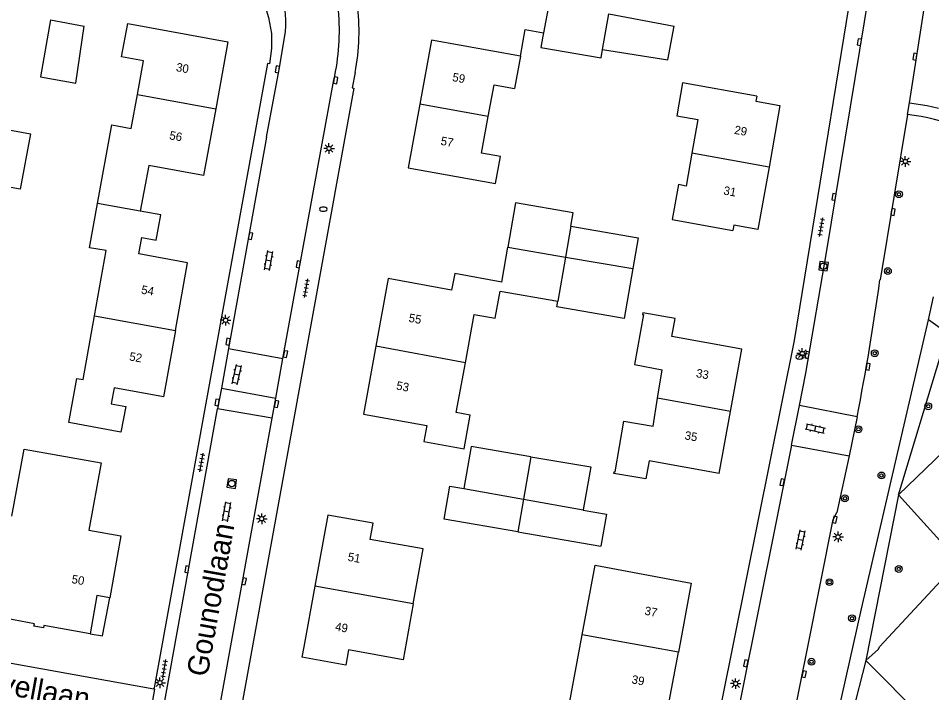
# Model space of a CAD drawing. Extents: x 132999 to 136000, y 398499 to 400501.
# Drawn here: x 133145.7 to 133253.2, y 398994.6 to 399074 of the extents above; entities that cross this region are included whole.
import ezdxf

# ---------------------------------------------------------------- set-up
doc = ezdxf.new("R2010")
doc.units = 0
for name, color, linetype in [('gg-afsc-erfafscheiding', 7, 'Continuous'), ('gg-afsc-muur', 7, 'Continuous'), ('gg-anno-huisnummerreeks BGT', 7, 'Continuous'), ('gg-anno-openbare ruimte label', 7, 'Continuous'), ('gg-bbg-bijgebouw', 7, 'Continuous'), ('gg-bbg-gedigitaliseerde bebouwing', 7, 'Continuous'), ('gg-bbg-gedigitaliseerde bijgebouw', 7, 'Continuous'), ('gg-bbg-hoofdgebouw', 7, 'Continuous'), ('gg-bbg-onder overbouw', 7, 'Continuous'), ('gg-bbg-pand overbouw', 7, 'Continuous'), ('gg-bbg-tussenscheiding', 7, 'Continuous'), ('gg-knt-verharding', 7, 'Continuous'), ('gt-grn-groengrens', 7, 'Continuous'), ('gt-grn-weggrens', 7, 'Continuous'), ('gt-symb-boom', 7, 'Continuous'), ('gt-symb-brandkraan', 7, 'Continuous'), ('gt-symb-klinker verharding', 7, 'Continuous'), ('gt-symb-kolk', 7, 'Continuous'), ('gt-symb-lichtmast', 7, 'Continuous'), ('gt-symb-rioolschacht', 7, 'Continuous'), ('gt-symb-tegel verharding', 7, 'Continuous')]:
    doc.layers.add(name, color=color, linetype=linetype)

# ---------------------------------------------------------------- blocks, each defined once
blk = doc.blocks.new('gt0-BOOM')
at = {"layer": 'gt-symb-boom'}
for radius in [0.4, 0.2]:
    blk.add_circle((0, 0), radius, dxfattribs=at)
blk = doc.blocks.new('gt0-KOLK')
at = {"layer": 'gt-symb-kolk'}
blk.add_lwpolyline([(0, 0), (0.37, 0), (0.37, 0.4), (-0.38, 0.4), (-0.38, 0), (0, 0)], dxfattribs=at)
blk = doc.blocks.new('gt0-TEG1')
at = {"layer": 'gt-symb-tegel verharding'}
for p, q in [((-1.12, 0), (1.12, 0)), ((-0.9, -0.25), (-0.9, 0.25)), ((-0.45, -0.25), (-0.45, 0.25)), ((0, -0.25), (0, 0.25)), ((0.45, -0.25), (0.45, 0.25)), ((0.9, -0.25), (0.9, 0.25))]:
    blk.add_line(p, q, dxfattribs=at)
blk = doc.blocks.new('gt0-LMAST')
at = {"layer": 'gt-symb-lichtmast'}
for p, q in [((-0.18, 0.17), (-0.45, 0.44)), ((-0.01, 0.25), (-0.01, 0.62)), ((0.17, 0.17), (0.44, 0.44)), ((-0.26, 0), (-0.63, 0)), ((-0.18, -0.18), (-0.45, -0.45)), ((-0.01, -0.25), (-0.01, -0.63)), ((0.44, -0.45), (0.17, -0.18)), ((0.24, 0), (0.62, 0))]:
    blk.add_line(p, q, dxfattribs=at)
blk.add_circle((-0.01, 0), 0.25, dxfattribs=at)
blk = doc.blocks.new('gt0-KL1')
at = {"layer": 'gt-symb-klinker verharding'}
for p, q in [((-1.15, 0.3), (1.15, 0.3)), ((-1, -0.3), (-1, 0.3)), ((-0.5, 0.3), (-0.5, 0.45)), ((0, -0.3), (0, 0.3)), ((0.5, 0.3), (0.5, 0.45)), ((1, -0.3), (1, 0.3)), ((-1.15, -0.3), (1.15, -0.3)), ((-0.5, -0.45), (-0.5, -0.3)), ((0.5, -0.45), (0.5, -0.3))]:
    blk.add_line(p, q, dxfattribs=at)
blk = doc.blocks.new('gt0-BR')
at = {"layer": 'gt-symb-brandkraan'}
for centre, radius, start, end in [((-0.24, 0), 0.206, 107.5669, 252.4331), ((0.6, -2.66), 3, 106.892, 107.5669), ((0, -0.69), 0.938, 73.108, 106.892), ((-0.6, -2.66), 3, 72.4331, 73.108), ((0.24, 0), 0.206, 287.567, 72.4331), ((0.6, 2.66), 3, 252.4331, 253.108), ((0, 0.69), 0.938, 253.108, 286.8921), ((-0.6, 2.66), 3, 286.8921, 287.567)]:
    blk.add_arc(centre, radius, start, end, dxfattribs=at)
blk = doc.blocks.new('gt0-RS')
at = {"layer": 'gt-symb-rioolschacht'}
blk.add_lwpolyline([(-0.5, -0.5), (0.5, -0.5), (0.5, 0.5), (-0.5, 0.5)], close=True, dxfattribs=at)
blk.add_circle((0, 0), 0.375, dxfattribs=at)

msp = doc.modelspace()

# ---------------------------------------------------------------- linework, layer by layer
at = {"layer": 'gg-afsc-erfafscheiding'}
msp.add_line((133252.84, 399038.49), (133253.46, 399041.19), dxfattribs=at)
msp.add_lwpolyline([(133239.4, 398979.64), (133244.97, 399004.49), (133252.84, 399038.49)], dxfattribs=at)
at = {"layer": 'gg-afsc-muur'}
msp.add_lwpolyline([(133204.83, 399069.52), (133205.39, 399072.69), (133207.56, 399072.29)], dxfattribs=at)
at = {"layer": 'gg-bbg-bijgebouw'}
for p, q in [((133208.22, 399075.81), (133207.56, 399072.29)), ((133149.54, 399073.82), (133153.47, 399073.05)), ((133207.56, 399072.29), (133207.48, 399071.87)), ((133213.13, 399021.2), (133212.22, 399016.11))]:
    msp.add_line(p, q, dxfattribs=at)
msp.add_lwpolyline([(133212.22, 399016.11), (133212.22, 399016.09), (133214.95, 399015.6), (133214.28, 399011.86)], dxfattribs=at)
at = {"layer": 'gg-bbg-gedigitaliseerde bebouwing'}
for p, q in [((133204.83, 399069.52), (133204.14, 399065.74)), ((133202.65, 399042.93), (133203.36, 399047.05)), ((133202.65, 399042.93), (133197.1, 399043.95)), ((133202.45, 399041.87), (133209.24, 399040.7)), ((133210.6, 398993.37), (133212.1, 399001.43))]:
    msp.add_line(p, q, dxfattribs=at)
for points in [[(133159.75, 399065.03), (133160.47, 399068.98), (133157.89, 399069.44), (133158.61, 399073.38)], [(133201.05, 399062.44), (133201.73, 399066.18), (133204.14, 399065.74)], [(133232.64, 399064.84), (133223.92, 399066.39), (133223.23, 399062.52), (133225.71, 399062.08), (133225, 399058.1)], [(133155.07, 399052.2), (133156.74, 399061.44), (133159.03, 399061.03), (133159.75, 399065.03)], [(133191.62, 399056.39), (133201.89, 399054.53), (133202.47, 399057.71), (133200.26, 399058.11), (133201.05, 399062.44)], [(133225, 399058.1), (133224.32, 399054.25), (133223.43, 399054.41), (133222.7, 399050.29), (133229.82, 399049.03)], [(133154.69, 399038.96), (133156.06, 399046.64), (133154.13, 399046.99), (133155.07, 399052.2)], [(133198.36, 399033.44), (133199.4, 399039.13), (133201.86, 399038.68), (133202.45, 399041.87)], [(133157.82, 399025.28), (133151.68, 399026.42), (133152.61, 399031.6), (133153.35, 399031.47), (133154.69, 399038.96)], [(133193.48, 399024.18), (133198.19, 399023.32), (133198.92, 399027.27), (133197.28, 399027.57), (133198.36, 399033.44)], [(133144.99, 399015.4), (133146.41, 399023.28), (133155.47, 399021.65)], [(133192.21, 399005.05), (133193.39, 399011.52), (133187.13, 399012.65), (133187.48, 399014.54), (133182.15, 399015.51)], [(133212.1, 399001.43), (133213.61, 399009.6), (133224.93, 399007.49)], [(133192.21, 399005.05), (133191.02, 398998.48), (133184.6, 398999.65), (133184.27, 398997.86), (133179.11, 398998.8)]]:
    msp.add_lwpolyline(points, dxfattribs=at)
at = {"layer": 'gg-bbg-gedigitaliseerde bijgebouw'}
for p, q in [((133215.23, 399074.51), (133222.92, 399073.07)), ((133206.05, 399022.36), (133213.13, 399021.2)), ((133204.53, 399013.54), (133214.28, 399011.86))]:
    msp.add_line(p, q, dxfattribs=at)
for points in [[(133149.54, 399073.82), (133148.36, 399067.1), (133152.52, 399066.34), (133153.47, 399073.05)], [(133214.49, 399070.31), (133222.17, 399069.1), (133222.92, 399073.07)], [(133207.48, 399071.87), (133207.24, 399070.57), (133214.33, 399069.35), (133214.49, 399070.31)], [(133145.97, 399053.86), (133140.05, 399054.95), (133141.19, 399061.49), (133147.15, 399060.38), (133145.97, 399053.86)], [(133210.78, 399049.51), (133211.05, 399051.08), (133204.25, 399052.26), (133203.36, 399047.05)], [(133210.78, 399049.51), (133218.68, 399048.15), (133218.06, 399044.53)], [(133218.06, 399044.53), (133217.05, 399038.65), (133209.12, 399040.02), (133209.24, 399040.7)], [(133206.05, 399022.36), (133199.05, 399023.59), (133198.16, 399018.64)], [(133204.53, 399013.54), (133195.85, 399015.04), (133196.52, 399018.93), (133198.16, 399018.64)]]:
    msp.add_lwpolyline(points, dxfattribs=at)
at = {"layer": 'gg-bbg-hoofdgebouw'}
for p, q in [((133194.37, 399071.42), (133192.98, 399063.9)), ((133204.83, 399069.52), (133194.37, 399071.42)), ((133192.98, 399063.9), (133191.62, 399056.39)), ((133229.55, 399027.71), (133230.89, 399035.05)), ((133220.97, 399029.29), (133221.51, 399032.62)), ((133228.22, 399020.41), (133229.55, 399027.71)), ((133182.15, 399015.51), (133180.63, 399007.16)), ((133224.93, 399007.49), (133223.42, 398999.37)), ((133221.88, 398991.28), (133223.42, 398999.37))]:
    msp.add_line(p, q, dxfattribs=at)
for points in [[(133158.61, 399073.38), (133170.4, 399071.23), (133168.97, 399063.35)], [(133232.64, 399064.84), (133232.52, 399064.23), (133235.38, 399063.71), (133234.09, 399056.45)], [(133168.97, 399063.35), (133167.54, 399055.48), (133161.08, 399056.68), (133160.08, 399051.29)], [(133234.09, 399056.45), (133232.79, 399049.14), (133229.93, 399049.65), (133229.82, 399049.03)], [(133164.22, 399037.24), (133165.64, 399045.2), (133159.92, 399046.26), (133160.27, 399048.17), (133161.94, 399047.86), (133162.49, 399050.85), (133160.08, 399051.29)], [(133197.1, 399043.95), (133196.72, 399041.99), (133189.28, 399043.35), (133187.82, 399035.38)], [(133230.89, 399035.05), (133222.66, 399036.55), (133223.04, 399038.64), (133219.24, 399039.33), (133219.2, 399039.13), (133219.32, 399039.11), (133218.25, 399033.22), (133221.51, 399032.62)], [(133164.22, 399037.24), (133162.82, 399029.42), (133157.03, 399030.48), (133156.68, 399028.59), (133158.37, 399028.28), (133157.82, 399025.28)], [(133187.82, 399035.38), (133186.35, 399027.41), (133193.83, 399026.04), (133193.48, 399024.18)], [(133228.22, 399020.41), (133219.97, 399021.9), (133219.58, 399019.76), (133215.84, 399020.42), (133215.87, 399020.62), (133215.97, 399020.61), (133216.99, 399026.55), (133220.44, 399025.96), (133220.97, 399029.29)], [(133155.47, 399021.65), (133154.03, 399013.75), (133157.79, 399013.07), (133156.49, 399005.77)], [(133180.63, 399007.16), (133179.33, 399000), (133179.11, 398998.8)], [(133154.18, 399001.52), (133148.73, 399002.5), (133148.68, 399002.24), (133147.58, 399002.45), (133147.63, 399002.71), (133144.35, 399003.32)]]:
    msp.add_lwpolyline(points, dxfattribs=at)
at = {"layer": 'gg-bbg-onder overbouw'}
msp.add_lwpolyline([(133156.49, 399005.77), (133154.99, 399006.04), (133154.18, 399001.52)], dxfattribs=at)
at = {"layer": 'gg-bbg-pand overbouw'}
msp.add_lwpolyline([(133154.18, 399001.52), (133155.66, 399001.28), (133156.49, 399005.77)], dxfattribs=at)
at = {"layer": 'gg-bbg-tussenscheiding'}
for p, q in [((133214.49, 399070.31), (133215.23, 399074.51)), ((133159.75, 399065.03), (133168.97, 399063.35)), ((133201.05, 399062.44), (133192.98, 399063.9)), ((133234.09, 399056.45), (133225, 399058.1)), ((133160.08, 399051.29), (133155.07, 399052.2)), ((133210.78, 399049.51), (133210.15, 399045.89)), ((133203.36, 399047.05), (133210.15, 399045.89)), ((133210.15, 399045.89), (133209.24, 399040.7)), ((133210.15, 399045.89), (133218.06, 399044.53)), ((133154.69, 399038.96), (133164.22, 399037.24)), ((133198.36, 399033.44), (133187.82, 399035.38)), ((133229.55, 399027.71), (133220.97, 399029.29)), ((133206.05, 399022.36), (133205.19, 399017.37)), ((133198.16, 399018.64), (133205.19, 399017.37)), ((133205.19, 399017.37), (133204.53, 399013.54)), ((133205.19, 399017.37), (133212.22, 399016.11)), ((133192.21, 399005.05), (133180.63, 399007.16)), ((133219.96, 399000), (133212.1, 399001.43)), ((133223.42, 398999.37), (133219.96, 399000))]:
    msp.add_line(p, q, dxfattribs=at)
at = {"layer": 'gg-knt-verharding'}
for p, q in [((133250.61, 399064.04), (133252.47, 399075.91)), ((133174.89, 399067.8), (133161.73, 398995.19)), ((133181.4, 399058.83), (133182.88, 399066.73)), ((133185.23, 399065.78), (133167.57, 398968.5)), ((133250.38, 399062.67), (133250.61, 399064.04)), ((133250.38, 399062.67), (133247.15, 399043.19)), ((133174.95, 399059.99), (133170.47, 399035.12)), ((133176.88, 399033.94), (133181.4, 399058.83)), ((133170.47, 399035.12), (133169.63, 399030.46)), ((133170.47, 399035.12), (133176.88, 399033.94)), ((133176.04, 399029.29), (133176.88, 399033.94)), ((133169.63, 399030.46), (133169.19, 399028.01)), ((133169.63, 399030.46), (133176.04, 399029.29)), ((133175.6, 399026.92), (133176.04, 399029.29)), ((133236.73, 399023.76), (133237.66, 399028.43)), ((133244.46, 399027.09), (133237.66, 399028.43)), ((133162.23, 398989.41), (133169.19, 399028.01)), ((133165.02, 398968.61), (133175.6, 399026.92)), ((133244.46, 399027.09), (133243.53, 399022.48)), ((133236.73, 399023.76), (133243.53, 399022.48)), ((133243.53, 399022.48), (133242.05, 399015.8)), ((133161.7, 398995.02), (133161.73, 398995.19))]:
    msp.add_line(p, q, dxfattribs=at)
for points in [[(133245.65, 399088.76), (133237.06, 399036.07), (133225.68, 398979.49), (133224.19, 398973.68), (133220.82, 398961.55)], [(133166.78, 399083.38), (133168.2, 399083.24), (133169.85, 399082.46), (133171.23, 399081.4), (133172.46, 399080.02), (133173.46, 399078.5), (133174.04, 399077.48), (133174.68, 399075.78), (133175.18, 399074.08), (133175.52, 399072.22), (133175.53, 399070.42), (133175.28, 399068.64), (133175.05, 399068.68), (133174.89, 399067.8)], [(133237.66, 399028.43), (133238.42, 399032.2), (133240.89, 399046.65), (133245.87, 399076.95)], [(133174.95, 399059.99), (133176.42, 399067.95), (133177.17, 399072.4)], [(133185.38, 399067.6), (133185.04, 399065.82), (133185.23, 399065.78)], [(133250.61, 399064.04), (133252.71, 399063.73), (133254.04, 399063.43)], [(133236.73, 399023.76), (133228.96, 398985.05), (133227.54, 398978.41), (133224.99, 398968.72), (133222.49, 398960.02)], [(133238.65, 399000), (133241.64, 399015), (133242.05, 399015.8)], [(133161.7, 398995.02), (133131.56, 399000.45), (133131.41, 398999.62), (133120.74, 399001.54), (133120.89, 399002.35), (133119.21, 399002.65), (133116.35, 399003.05), (133112.5, 399003.39)], [(133227.46, 398954.52), (133229.57, 398960.86), (133231.97, 398969.81), (133234.29, 398978.78), (133234.98, 398981.91), (133236.16, 398987.56), (133238.65, 399000)], [(133160.87, 398989.66), (133161.82, 398995), (133161.7, 398995.02)]]:
    msp.add_lwpolyline(points, dxfattribs=at)
for centre, radius, start, end in [((133167.17, 399073.47), 10.06, 353.9239, 25.2299), ((133159.78, 399072.47), 26.06, 349.2175, 7.2805), ((133156.52, 399072.57), 27, 347.5034, 4.9476), ((133247.13, 399036.61), 26.26, 54.8202, 82.8871), ((132935.85, 399086.95), 314.36, 349.0229, 351.9982)]:
    msp.add_arc(centre, radius, start, end, dxfattribs=at)
at = {"layer": 'gt-grn-groengrens'}
for p, q in [((133256.06, 399036.18), (133252.84, 399038.49)), ((133249.33, 399017.91), (133254.32, 399034.39)), ((133260.35, 399028.51), (133249.33, 399017.91)), ((133249.33, 399017.91), (133245.47, 398998.38)), ((133245.47, 398998.38), (133240.62, 398979.37))]:
    msp.add_line(p, q, dxfattribs=at)
for points in [[(133245.47, 398998.38), (133246.97, 398999.74), (133247.11, 399000), (133256.43, 399010.05), (133249.33, 399017.91)], [(133244.02, 398982.88), (133245.88, 398984.8), (133248.37, 398987.31), (133252.17, 398991.68), (133245.47, 398998.38)]]:
    msp.add_lwpolyline(points, dxfattribs=at)
at = {"layer": 'gt-grn-weggrens'}
msp.add_line((133175.6, 399026.92), (133169.19, 399028.01), dxfattribs=at)

# ---------------------------------------------------------------- block references
at = {"layer": 'gt-symb-boom'}
for p in [(133249.38, 399053.28), (133248.08, 399044.23), (133246.53, 399034.56), (133252.83, 399028.32), (133244.62, 399025.61), (133247.32, 399020.18), (133243.02, 399017.48), (133249.36, 399009.17), (133241.21, 399007.61), (133243.86, 399003.37), (133239.09, 398998.25)]:
    msp.add_blockref('gt0-BOOM', p, dxfattribs=at)
at = {"layer": 'gt-symb-brandkraan'}
for p in [(133181.63, 399051.53), (133237.69, 399034.13)]:
    msp.add_blockref('gt0-BR', p, dxfattribs=at)
at = {"layer": 'gt-symb-klinker verharding'}
for p, rotation in [((133175.2, 399045.47), 79.98206552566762), ((133171.45, 399032.04), 77.93725397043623), ((133239.54, 399025.69), -12.590950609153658), ((133170.26, 399015.9), 79.56697526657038), ((133237.82, 399012.57), 78.63386214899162)]:
    msp.add_blockref('gt0-KL1', p, dxfattribs=dict(at, rotation=rotation))
at = {"layer": 'gt-symb-kolk'}
for p, rotation in [((133244.92, 399071.16), 80.4999894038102), ((133251.45, 399069.44), 80.79203094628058), ((133176.42, 399067.95), 79.59698632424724), ((133182.88, 399066.73), -100.59933094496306), ((133241.92, 399052.94), 80.20785375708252), ((133248.48, 399051.22), -99.20796905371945), ((133172.86, 399048.38), -100.07433273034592), ((133178.88, 399045), 79.925667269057), ((133170.61, 399035.9), 79.80279442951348), ((133176.98, 399034.49), -100.30997039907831), ((133238.77, 399034.33), 79.45426563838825), ((133245.55, 399033.01), -99.44347491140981), ((133169.32, 399028.74), 79.63367739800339), ((133175.92, 399028.62), -100.25359802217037), ((133235.84, 399019.35), 79.16208955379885), ((133241.64, 399015), -101.29870020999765), ((133165.78, 399009.1), 79.98206552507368), ((133172.12, 399007.73), -99.90507920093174), ((133231.56, 398998.01), 78.70129979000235), ((133238.02, 398996.82), -101.29870021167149)]:
    msp.add_blockref('gt0-KOLK', p, dxfattribs=dict(at, rotation=rotation))
at = {"layer": 'gt-symb-lichtmast'}
for p in [(133182.31, 399058.67), (133250.14, 399057.14), (133170.14, 399038.45), (133238.01, 399034.53), (133174.39, 399015.08), (133242.22, 399012.94), (133162.42, 398995.78), (133230.17, 398995.67)]:
    msp.add_blockref('gt0-LMAST', p, dxfattribs=at)
at = {"layer": 'gt-symb-rioolschacht'}
for p, rotation in [((133240.51, 399044.81), -97.64386978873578), ((133170.86, 399019.22), -97.93555036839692)]:
    msp.add_blockref('gt0-RS', p, dxfattribs=dict(at, rotation=rotation))
at = {"layer": 'gt-symb-tegel verharding'}
for p, rotation in [((133240.23, 399049.4), 80.6789392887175), ((133179.61, 399042.21), 80.15137761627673), ((133167.28, 399021.7), 79.80279442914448), ((133162.9, 398997.42), -99.09480497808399)]:
    msp.add_blockref('gt0-TEG1', p, dxfattribs=dict(at, rotation=rotation))

# ---------------------------------------------------------------- texts
at = {"layer": 'gg-anno-huisnummerreeks BGT'}
for s, rotation, p in [('30', 349.7, (133164.24, 399067.78)), ('59', 349.6, (133196.76, 399066.61)), ('56', 349.7, (133163.46, 399059.76)), ('29', 349.9, (133229.94, 399060.4)), ('57', 349.7, (133195.39, 399059.1)), ('31', 349.9, (133228.67, 399053.26)), ('54', 349.9, (133160.14, 399041.59)), ('55', 349.6, (133191.62, 399038.27)), ('52', 349.9, (133158.74, 399033.73)), ('33', 349.7, (133225.44, 399031.76)), ('53', 349.6, (133190.16, 399030.3)), ('35', 349.7, (133224.1, 399024.44)), ('51', 349.7, (133184.45, 399010.14)), ('50', 349.9, (133151.95, 399007.51)), ('37', 349.5, (133219.38, 399003.79)), ('49', 349.7, (133182.96, 399001.93)), ('39', 349.3, (133217.86, 398995.71))]:
    msp.add_text(s, height=1, rotation=rotation, dxfattribs=at).set_placement(p)
at = {"layer": 'gg-anno-openbare ruimte label'}
for s, rotation, p in [('Gounodlaan', 79.9, (133167.99, 398996.38)), ('Ravellaan', 349.7, (133139.29, 398995.28))]:
    msp.add_text(s, height=2.5, rotation=rotation, dxfattribs=at).set_placement(p)

doc.saveas('drawing.dxf')
